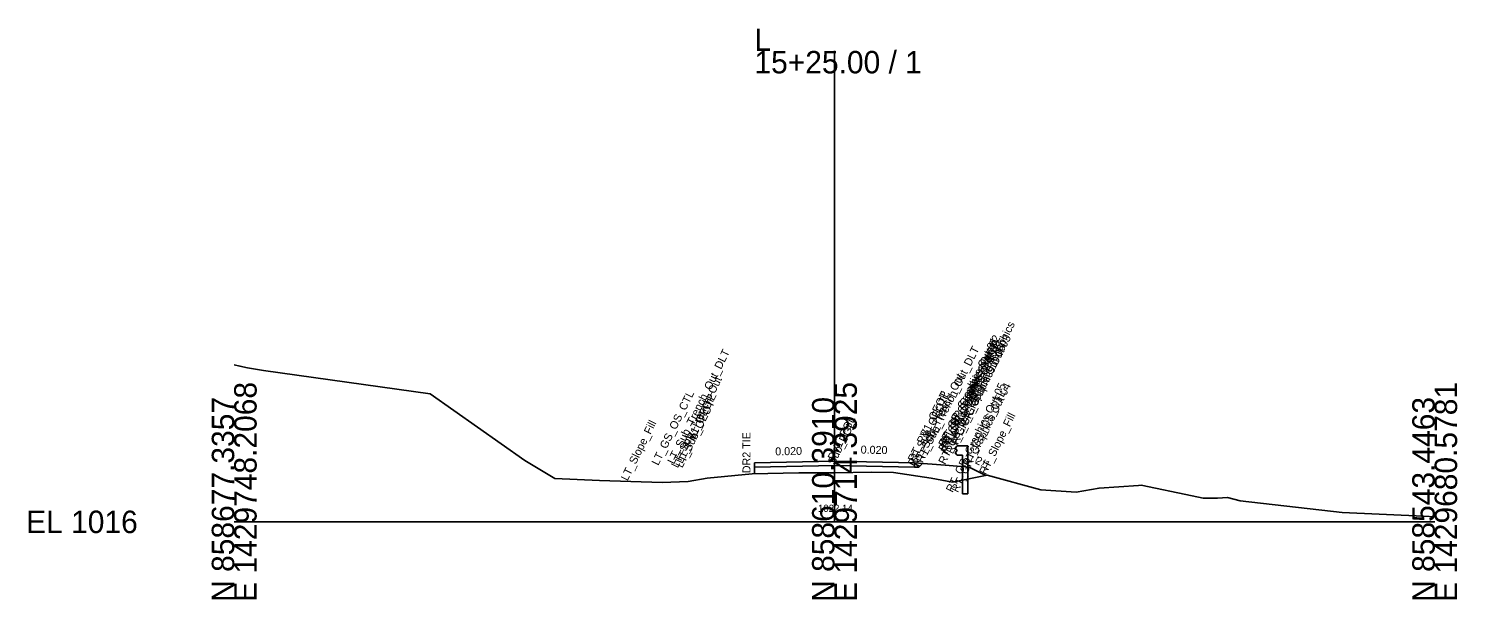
# Model space of a CAD drawing. Extents: x -26 to 153, y -10 to 13058.
# Drawn here: x -25.7 to 152.8, y 7490.3 to 7561.6 of the extents above; entities that cross this region are included whole.
import ezdxf

# ---------------------------------------------------------------- set-up
doc = ezdxf.new("R2010")
doc.units = 0
for name, color, linetype in [('Exist Cross Section Cell', 7, 'Continuous'), ('Exist XS Center Line Elevation Label', 7, 'Continuous'), ('Exist XS Ground Line', 7, 'Continuous'), ('Prop CMT Guardrail Graphics', 7, 'Continuous'), ('Prop CMT Pvmt Course 1', 7, 'Continuous'), ('Prop CMT Pvmt Surface', 7, 'Continuous'), ('Prop CMT Pvmt Surface Shoulder', 7, 'Continuous'), ('Prop CMT Shld Paved Course 1', 7, 'Continuous'), ('Prop CMT Slope Grass', 7, 'Continuous'), ('Prop CMT Subgrade Earthwork', 7, 'Continuous'), ('Prop XS Dump Level', 7, 'Continuous'), ('Prop XS SE Text', 7, 'Continuous'), ('Prop XS Side Slope Text', 7, 'Continuous'), ('Prop XSC Text', 7, 'Continuous')]:
    doc.layers.add(name, color=color, linetype=linetype)

msp = doc.modelspace()

# ---------------------------------------------------------------- linework, layer by layer
at = {"layer": 'Exist Cross Section Cell'}
for p, q in [((75, 7500), (75, 7558.84)), ((0, 7500), (75, 7500)), ((75, 7500), (150, 7500))]:
    msp.add_line(p, q, dxfattribs=at)
at = {"layer": 'Exist XS Ground Line'}
msp.add_lwpolyline([(0, 7519.61), (0.71, 7519.47), (1.67, 7519.25), (3.65, 7518.93), (24.5, 7515.98), (36.31, 7507.68), (40.06, 7505.43), (45.63, 7505.15), (53.46, 7504.93), (56.72, 7505.03), (59.11, 7505.44), (64.72, 7506.01), (70.54, 7506.11), (73.64, 7506.13), (75, 7506.14), (79.63, 7506.19), (82.39, 7506.18), (87.07, 7505.47), (89.77, 7504.96), (94.08, 7505.83), (100.77, 7504.01), (105.19, 7503.69), (108.07, 7504.22), (113.01, 7504.56), (113.32, 7504.57), (119.69, 7503.26), (121.09, 7502.96), (122.86, 7502.97), (124.11, 7503.04), (125.68, 7502.64), (138.45, 7501.15), (148.62, 7500.7), (150, 7500.61)], dxfattribs=at)
at = {"layer": 'Prop CMT Guardrail Graphics'}
for points in [[(91.68, 7509.49), (90.35, 7509.49), (90.07, 7509.2)], [(90.07, 7509.2), (90.35, 7508.9)], [(91.68, 7503.49), (91.68, 7509.49)], [(90.35, 7508.9), (90.07, 7508.61)], [(90.07, 7508.61), (90.35, 7508.32), (91.01, 7508.32)], [(91.01, 7508.32), (91.01, 7503.49)], [(91.01, 7503.49), (91.68, 7503.49)]]:
    msp.add_lwpolyline(points, dxfattribs=at)
at = {"layer": 'Prop CMT Pvmt Course 1'}
for points in [[(75, 7507.59), (65, 7507.39)], [(65, 7507.39), (65, 7506.85)], [(75, 7507.05), (75, 7507.59)], [(75, 7507.59), (85, 7507.39)], [(75, 7507.05), (75, 7507.59)], [(85, 7507.39), (85, 7506.85)], [(65, 7506.85), (75, 7507.05)], [(85, 7506.85), (75, 7507.05)]]:
    msp.add_lwpolyline(points, dxfattribs=at)
at = {"layer": 'Prop CMT Pvmt Surface'}
for points in [[(75, 7507.59), (65, 7507.39)], [(75, 7507.59), (85, 7507.39)]]:
    msp.add_lwpolyline(points, dxfattribs=at)
at = {"layer": 'Prop CMT Pvmt Surface Shoulder'}
for points in [[(65, 7507.39), (65, 7507.39)], [(85, 7507.39), (85, 7507.39)]]:
    msp.add_lwpolyline(points, dxfattribs=at)
at = {"layer": 'Prop CMT Shld Paved Course 1'}
for points in [[(65, 7507.39), (65, 7507.39)], [(65, 7506.85), (65, 7507.39)], [(85, 7507.39), (85, 7507.39)], [(85, 7507.39), (85.55, 7506.84)], [(85, 7506.85), (85, 7507.39)], [(85.55, 7506.84), (85, 7506.85)]]:
    msp.add_lwpolyline(points, dxfattribs=at)
at = {"layer": 'Prop CMT Slope Grass'}
for points in [[(85, 7507.39), (88.82, 7507.09)], [(88.82, 7507.09), (91.82, 7506.85)], [(91.82, 7506.85), (93.93, 7505.79)]]:
    msp.add_lwpolyline(points, dxfattribs=at)
at = {"layer": 'Prop CMT Subgrade Earthwork'}
for points in [[(85.55, 7506.84), (86.02, 7507.31)], [(75, 7507.05), (65, 7506.85)], [(75, 7507.05), (85, 7506.85)], [(85, 7506.85), (85.55, 7506.84)]]:
    msp.add_lwpolyline(points, dxfattribs=at)
at = {"layer": 'Prop XSC Text'}
msp.add_line((65, 7506.85), (65, 7506.02), dxfattribs=at)

# ---------------------------------------------------------------- texts
at = {"layer": 'Exist Cross Section Cell'}
for s, p in [('L', (65, 7558.84)), ('15+25.00 / 1', (65, 7556.04)), ('EL 1016', (-26, 7498.6))]:
    msp.add_text(s, height=2.8, dxfattribs=at).set_placement(p)
for s, p in [('E 1429748.2068', (2.8, 7490)), ('E 1429714.3925', (77.8, 7490)), ('E 1429680.5781', (152.8, 7490)), ('N 858677.3357', (0, 7490)), ('N 858610.3910', (75, 7490)), ('N 858543.4463', (150, 7490))]:
    msp.add_text(s, height=2.8, rotation=90, dxfattribs=at).set_placement(p)
at = {"layer": 'Exist XS Center Line Elevation Label'}
msp.add_text('1022.14', height=0.9, dxfattribs=at).set_placement((72.94, 7501.24))
msp.add_text('1022.14', height=0.9, dxfattribs=at).set_placement((72.94, 7501.24))
msp.add_text('1022.14', height=0.9, dxfattribs=at).set_placement((72.94, 7501.24))
at = {"layer": 'Prop XS Dump Level'}
for s, p in [('RT_GS_OS_GR_Face_Graphics', (88.82, 7507.09)), ('LT_Sub_Trench_Out_DLT', (54.95, 7507.13)), ('RT_Sub_Trench_Out_DLT', (86.02, 7507.31)), ('RT_GR_Graphics Out 01', (88.82, 7509.3)), ('RT_GR_Graphics Out 08', (88.82, 7508.71)), ('RT_GR_Graphics Out 02', (89.09, 7509.59)), ('RT_GR_Graphics Out 09', (89.09, 7509)), ('RT_GR_Graphics Out 07', (89.09, 7508.42)), ('RT_GR_Graphics Out 06', (89.76, 7508.42)), ('RT_GR_Graphics Out 03', (90.42, 7509.59)), ('LT_Sub_Trench_Out', (55.42, 7506.66)), ('RT_Sub_Trench_Out', (85.55, 7506.84)), ('RT_PV1_OEOT', (85, 7507.39)), ('RT_PS1_OEOP', (85, 7507.39)), ('RT_GR_Graphics Out 05', (89.76, 7503.59)), ('RT_GR_Graphics Out 04', (90.42, 7503.59)), ('LT_GS_OS_CTL', (52.98, 7506.97)), ('LT_PV1_OEOT', (55.98, 7507.21)), ('LT_PS1_OEOP', (55.98, 7507.21)), ('LT_Sub_OEOT', (55.98, 7506.67)), ('RT_Sub_OEOT', (85, 7506.85)), ('RT_GS_OS_CTL', (91.82, 7506.85)), ('LT_Slope_Fill', (49.14, 7505.05)), ('PV1_PGL', (75, 7507.59)), ('RT_Slope_Fill', (93.92, 7505.8)), ('Sub_PGL', (75, 7507.05))]:
    msp.add_text(s, height=1, rotation=63.5833, dxfattribs=at).set_placement(p)
at = {"layer": 'Prop XS SE Text'}
for rotation, p in [(1.1458, (67.61, 7508.3)), (358.8542, (78.27, 7508.53))]:
    msp.add_text('0.020', height=1, rotation=rotation, dxfattribs=at).set_placement(p)
at = {"layer": 'Prop XS Side Slope Text'}
msp.add_text('2:1', height=1, rotation=333.4349, dxfattribs=at).set_placement((92.5, 7507.35))
at = {"layer": 'Prop XSC Text'}
msp.add_text('DR2 TIE', height=1, rotation=90, dxfattribs=at).set_placement((64.51, 7506.08))

doc.saveas('drawing.dxf')
